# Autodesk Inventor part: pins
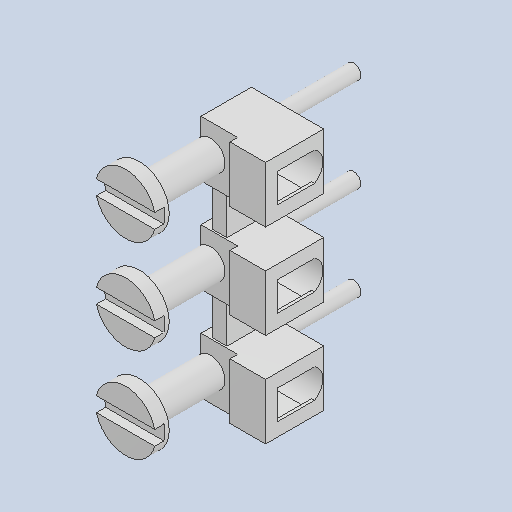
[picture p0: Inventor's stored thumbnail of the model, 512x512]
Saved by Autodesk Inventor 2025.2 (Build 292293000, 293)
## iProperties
Created: 2025-04
Part Number: pins
Material: Generic
Description: PART--DESC
Document SubType Name: Modeling
Designer: BennF
Density: 1 g/cm^3
Appearance: Default
Author: BennF
Revision Number: NONE
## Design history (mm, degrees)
feature "Solid1"
body "Solid2"
